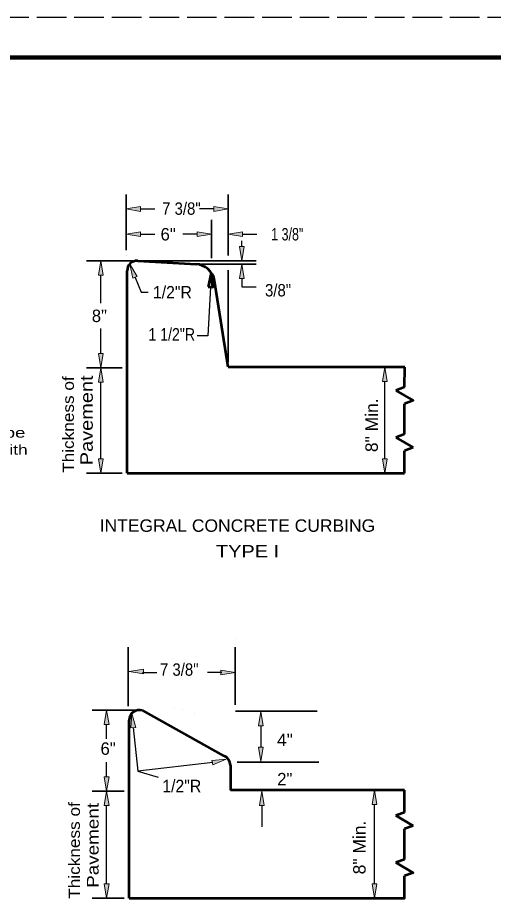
# Model space of a CAD drawing. Extents: x 36.6 to 71.9, y 0.8 to 22.8.
# Drawn here: x 48.52 to 54.49, y 11.71 to 22.78 of the extents above; entities that cross this region are included whole.
import ezdxf

# ---------------------------------------------------------------- set-up
doc = ezdxf.new("R2010")
doc.units = 0
doc.header["$LTSCALE"] = 0.062
doc.linetypes.add('LONG_DASHED', pattern=[7.5, 6, -1.5])
for name, color, linetype, lineweight in [('1', 7, 'Continuous', 13), ('3', 7, 'Continuous', 25), ('8', 7, 'Continuous', 13)]:
    doc.layers.add(name, color=color, linetype=linetype, lineweight=lineweight)

msp = doc.modelspace()

# ---------------------------------------------------------------- hatches: boundary and pattern name
at = {"layer": '1'}
for points in [[(50.06183, 20.34408), (50.06183, 20.40408), (49.88183, 20.37408), (49.88183, 20.37408)], [(50.9835, 20.34408), (50.9835, 20.40408), (51.1635, 20.37408), (51.1635, 20.37408)], [(50.06158, 20.02625), (50.06158, 20.08625), (49.88158, 20.05625), (49.88158, 20.05625)], [(50.7735, 20.02625), (50.7735, 20.08625), (50.9535, 20.05625), (50.9535, 20.05625)], [(50.7735, 20.02625), (50.7735, 20.08625), (50.9535, 20.05625), (50.9535, 20.05625)], [(51.3435, 20.02625), (51.3435, 20.08625), (51.1635, 20.05625), (51.1635, 20.05625)], [(51.36367, 19.90225), (51.30367, 19.90225), (51.33367, 19.72217), (51.33367, 19.72217)], [(49.59175, 19.54208), (49.53175, 19.54208), (49.56175, 19.72208), (49.56175, 19.72208)], [(51.36367, 19.50067), (51.30367, 19.50067), (51.33367, 19.68067), (51.33367, 19.68067)], [(49.59175, 18.55858), (49.53175, 18.55858), (49.56175, 18.37858), (49.56175, 18.37858)], [(49.59175, 18.19867), (49.53175, 18.19867), (49.56175, 18.37867), (49.56175, 18.37867)], [(53.15983, 18.20775), (53.09983, 18.20775), (53.12983, 18.38775), (53.12983, 18.38775)], [(49.59175, 17.23508), (49.53175, 17.23508), (49.56175, 17.055), (49.56175, 17.055)], [(53.15983, 17.23508), (53.09983, 17.23508), (53.12983, 17.055), (53.12983, 17.055)], [(50.09767, 14.532), (50.09767, 14.592), (49.91767, 14.562), (49.91767, 14.562)], [(51.07008, 14.52), (51.07008, 14.58), (51.25008, 14.55), (51.25008, 14.55)], [(49.66608, 13.89575), (49.60608, 13.89575), (49.63608, 14.07575), (49.63608, 14.07575)], [(51.60333, 13.87817), (51.54333, 13.87817), (51.57333, 14.05817), (51.57333, 14.05817)], [(51.60333, 13.61), (51.54333, 13.61), (51.57333, 13.43), (51.57333, 13.43)], [(49.66608, 13.23983), (49.60608, 13.23983), (49.63608, 13.05983), (49.63608, 13.05983)], [(53.03125, 12.89117), (52.97125, 12.89117), (53.00125, 13.07117), (53.00125, 13.07117)], [(49.66608, 12.87983), (49.60608, 12.87983), (49.63608, 13.05983), (49.63608, 13.05983)], [(51.61608, 12.87967), (51.55608, 12.87967), (51.58608, 13.05967), (51.58608, 13.05967)], [(49.66608, 11.89183), (49.60608, 11.89183), (49.63608, 11.71183), (49.63608, 11.71183)], [(53.03125, 11.89183), (52.97125, 11.89183), (53.00125, 11.71183), (53.00125, 11.71183)]]:
    msp.add_hatch(color=256, dxfattribs=at).paths.add_polyline_path(points)
at = {"layer": '3'}
for points in [[(49.96558, 19.50317), (50.02125, 19.5255), (49.92633, 19.68133), (49.92633, 19.68133)], [(50.91083, 19.39458), (50.97075, 19.39125), (50.95092, 19.57258), (50.95092, 19.57258)], [(49.94142, 13.85375), (50.00108, 13.85992), (49.95275, 14.03592), (49.95275, 14.03592)], [(50.95742, 13.44542), (50.97167, 13.38708), (51.13942, 13.45867), (51.13942, 13.45867)]]:
    msp.add_hatch(color=256, dxfattribs=at).paths.add_polyline_path(points)

# ---------------------------------------------------------------- linework, layer by layer
at = {"layer": '1', "linetype": 'LONG_DASHED', "lineweight": 25}
msp.add_line((71.78558, 22.77842), (36.58558, 22.77842), dxfattribs=at)
at = {"layer": '1', "lineweight": 158}
msp.add_line((71.70225, 22.27842), (39.20225, 22.27842), dxfattribs=at)
at = {"layer": '1', "lineweight": 35}
for p, q in [((49.88158, 20.11875), (49.88158, 20.55408)), ((51.1635, 19.78867), (51.1635, 20.55408)), ((49.88158, 19.857), (49.88158, 20.23625)), ((50.9535, 19.75733), (50.9535, 20.23625)), ((51.1635, 20.1125), (51.1635, 20.23625)), ((49.9635, 19.72217), (49.38175, 19.72217)), ((50.0885, 19.72225), (51.51367, 19.72225)), ((50.8215, 19.68067), (51.51367, 19.68067)), ((51.1635, 18.45025), (51.1635, 19.60558)), ((49.83142, 18.37867), (49.38175, 18.37867)), ((49.83142, 17.05508), (49.38175, 17.05508)), ((49.90567, 14.12725), (49.90567, 14.86658)), ((51.25008, 14.74908), (51.25008, 14.86658)), ((51.25008, 14.14433), (51.25008, 14.86658)), ((49.90567, 14.74908), (49.90567, 14.79217)), ((49.99758, 14.07575), (49.45608, 14.07575)), ((51.25658, 14.06308), (52.2825, 14.06308)), ((51.27567, 13.42233), (52.30158, 13.42233)), ((49.8575, 13.05983), (49.45608, 13.05983)), ((49.8575, 11.71183), (49.45608, 11.71183))]:
    msp.add_line(p, q, dxfattribs=at)
at = {"layer": '1', "lineweight": 25}
for p, q in [((50.06183, 20.37408), (50.24183, 20.37408)), ((50.9835, 20.37408), (50.8035, 20.37408)), ((50.06158, 20.05625), (50.24075, 20.05625)), ((50.7735, 20.05625), (50.5935, 20.05625)), ((51.3435, 20.05625), (51.5235, 20.05625)), ((51.33367, 19.90225), (51.33367, 19.97342)), ((49.56175, 19.18992), (49.56175, 19.54217)), ((51.33367, 19.50067), (51.33367, 19.39667)), ((51.33367, 19.39667), (51.51367, 19.39667)), ((49.56175, 18.55858), (49.56175, 18.87142)), ((49.56175, 17.23508), (49.56175, 18.19867)), ((53.12983, 17.23508), (53.12983, 18.20775)), ((50.08567, 14.55), (50.26567, 14.55)), ((51.08217, 14.54992), (50.90217, 14.54992)), ((49.63608, 13.71692), (49.63608, 13.89575)), ((51.57192, 13.87875), (51.57192, 13.60942)), ((49.63608, 13.23983), (49.63608, 13.424)), ((49.63608, 11.89183), (49.63608, 12.87983)), ((51.58458, 12.88017), (51.58458, 12.61083)), ((51.58458, 12.88017), (51.58458, 12.61083)), ((53.00125, 11.89183), (53.00125, 12.89117))]:
    msp.add_line(p, q, dxfattribs=at)
at = {"layer": '1'}
for p, q in [((50.7735, 20.05625), (50.70175, 20.05625)), ((50.9535, 19.99375), (50.9535, 19.87625)), ((49.62425, 18.37858), (49.74175, 18.37858)), ((53.06733, 18.38775), (52.94983, 18.38775)), ((53.19233, 17.05508), (53.30983, 17.05508)), ((53.06375, 13.07117), (53.18125, 13.07117)), ((49.69858, 13.05983), (49.81608, 13.05983)), ((53.06375, 11.71183), (53.18125, 11.71183))]:
    msp.add_line(p, q, dxfattribs=at)
at = {"layer": '1', "lineweight": 53}
for p, q in [((50.026, 19.72225), (50.759, 19.68067)), ((49.89392, 17.05508), (49.89392, 19.59742)), ((51.1635, 18.38775), (50.99175, 19.47)), ((53.38425, 18.38775), (51.1635, 18.38775)), ((53.37892, 18.13408), (53.38425, 18.38775)), ((53.37892, 18.13408), (53.27075, 18.09417)), ((53.37892, 17.54317), (53.37892, 17.9265)), ((53.37892, 17.54317), (53.27075, 17.50325)), ((53.27075, 17.50325), (53.48717, 17.3755)), ((53.48717, 17.3755), (53.37892, 17.33558)), ((53.37892, 17.05508), (53.37892, 17.33558)), ((49.89392, 17.05508), (53.37892, 17.05508)), ((50.08517, 14.06992), (51.10542, 13.50158)), ((49.92, 11.71183), (49.92, 13.95158)), ((51.19017, 13.38325), (51.19017, 13.07117)), ((53.37892, 13.07117), (51.19017, 13.07117)), ((53.37892, 12.79083), (53.37892, 13.07117)), ((53.37892, 12.79083), (53.27075, 12.75092)), ((53.27075, 12.75092), (53.48717, 12.62317)), ((53.48717, 12.62317), (53.37892, 12.58325)), ((53.37892, 12.19992), (53.37892, 12.58325)), ((53.37892, 12.19992), (53.27075, 12.16))]:
    msp.add_line(p, q, dxfattribs=at)
at = {"layer": '1'}
for points in [[(50.06183, 20.34408), (50.06183, 20.40408), (49.88183, 20.37408), (49.88183, 20.37408)], [(50.9835, 20.34408), (50.9835, 20.40408), (51.1635, 20.37408), (51.1635, 20.37408)], [(50.06158, 20.02625), (50.06158, 20.08625), (49.88158, 20.05625), (49.88158, 20.05625)], [(50.7735, 20.02625), (50.7735, 20.08625), (50.9535, 20.05625), (50.9535, 20.05625)], [(50.7735, 20.02625), (50.7735, 20.08625), (50.9535, 20.05625), (50.9535, 20.05625)], [(51.3435, 20.02625), (51.3435, 20.08625), (51.1635, 20.05625), (51.1635, 20.05625)], [(51.36367, 19.90225), (51.30367, 19.90225), (51.33367, 19.72217), (51.33367, 19.72217)], [(49.59175, 19.54208), (49.53175, 19.54208), (49.56175, 19.72208), (49.56175, 19.72208)], [(51.36367, 19.50067), (51.30367, 19.50067), (51.33367, 19.68067), (51.33367, 19.68067)], [(49.59175, 18.55858), (49.53175, 18.55858), (49.56175, 18.37858), (49.56175, 18.37858)], [(49.59175, 18.19867), (49.53175, 18.19867), (49.56175, 18.37867), (49.56175, 18.37867)], [(53.15983, 18.20775), (53.09983, 18.20775), (53.12983, 18.38775), (53.12983, 18.38775)], [(49.59175, 17.23508), (49.53175, 17.23508), (49.56175, 17.055), (49.56175, 17.055)], [(53.15983, 17.23508), (53.09983, 17.23508), (53.12983, 17.055), (53.12983, 17.055)], [(50.09767, 14.532), (50.09767, 14.592), (49.91767, 14.562), (49.91767, 14.562)], [(51.07008, 14.52), (51.07008, 14.58), (51.25008, 14.55), (51.25008, 14.55)], [(49.66608, 13.89575), (49.60608, 13.89575), (49.63608, 14.07575), (49.63608, 14.07575)], [(51.60333, 13.87817), (51.54333, 13.87817), (51.57333, 14.05817), (51.57333, 14.05817)], [(51.60333, 13.61), (51.54333, 13.61), (51.57333, 13.43), (51.57333, 13.43)], [(49.66608, 13.23983), (49.60608, 13.23983), (49.63608, 13.05983), (49.63608, 13.05983)], [(53.03125, 12.89117), (52.97125, 12.89117), (53.00125, 13.07117), (53.00125, 13.07117)], [(49.66608, 12.87983), (49.60608, 12.87983), (49.63608, 13.05983), (49.63608, 13.05983)], [(51.61608, 12.87967), (51.55608, 12.87967), (51.58608, 13.05967), (51.58608, 13.05967)], [(49.66608, 11.89183), (49.60608, 11.89183), (49.63608, 11.71183), (49.63608, 11.71183)], [(53.03125, 11.89183), (52.97125, 11.89183), (53.00125, 11.71183), (53.00125, 11.71183)]]:
    msp.add_lwpolyline(points, close=True, dxfattribs=at)
at = {"layer": '1', "lineweight": 53}
for points in [[(53.27075, 18.09417), (53.48717, 17.96642), (53.37892, 17.9265)], [(53.27075, 12.16), (53.48717, 12.03225), (53.37892, 11.99233)], [(49.92, 11.71183), (53.37892, 11.71183), (53.37892, 11.99233)]]:
    msp.add_lwpolyline(points, dxfattribs=at)
for centre, radius, start, end in [((50.01892, 19.59742), 0.125, 86.75472, 180), ((50.74483, 19.43108), 0.25, 8.96004, 86.75471), ((50.045, 13.95158), 0.125, 71.23187, 180), ((51.06517, 13.38325), 0.125, 0, 71.23187)]:
    msp.add_arc(centre, radius, start, end, dxfattribs=at)
at = {"layer": '3'}
msp.add_line((50.97042, 13.41858), (50.02758, 13.31117), dxfattribs=at)
at = {"layer": '3', "lineweight": 13}
for points in [[(49.96558, 19.50317), (50.02125, 19.5255), (49.92633, 19.68133), (49.92633, 19.68133)], [(49.94142, 13.85375), (50.00108, 13.85992), (49.95275, 14.03592), (49.95275, 14.03592)], [(50.95742, 13.44542), (50.97167, 13.38708), (51.13942, 13.45867), (51.13942, 13.45867)]]:
    msp.add_lwpolyline(points, close=True, dxfattribs=at)
at = {"layer": '3'}
for points in [[(49.99342, 19.51433), (50.06858, 19.32708), (50.15583, 19.32708)], [(50.94083, 19.39292), (50.90642, 18.78142), (50.77367, 18.78142)], [(49.97125, 13.85683), (50.02758, 13.31117), (50.28158, 13.23558)]]:
    msp.add_lwpolyline(points, dxfattribs=at)
at = {"layer": '3', "lineweight": 53}
msp.add_lwpolyline([(50.91083, 19.39458), (50.97075, 19.39125), (50.95092, 19.57258), (50.95092, 19.57258)], close=True, dxfattribs=at)
at = {"layer": '8'}
for p, q in [((51.1635, 20.37408), (51.16358, 20.37408)), ((49.88158, 20.05625), (49.88167, 20.05625)), ((50.9535, 20.05625), (50.95358, 20.05625)), ((50.9535, 20.05625), (50.95358, 20.05625)), ((51.1635, 20.05625), (51.16358, 20.05625)), ((51.1635, 20.05), (51.16358, 20.05)), ((49.56175, 19.72217), (49.56183, 19.72217)), ((49.88158, 19.7945), (49.88167, 19.7945)), ((50.026, 19.72225), (50.02608, 19.72225)), ((50.026, 19.72217), (50.02608, 19.72217)), ((50.759, 19.68067), (50.75908, 19.68067)), ((50.9535, 19.69483), (50.95358, 19.69483)), ((51.33367, 19.68067), (51.33375, 19.68067)), ((49.56175, 18.37867), (49.56183, 18.37867)), ((49.56175, 18.37858), (49.56183, 18.37858)), ((49.89392, 18.37867), (49.894, 18.37867)), ((51.1635, 18.38775), (51.16358, 18.38775)), ((53.12983, 18.38775), (53.12992, 18.38775)), ((53.12983, 18.38775), (53.12992, 18.38775)), ((49.89392, 17.05508), (49.894, 17.05508)), ((53.12983, 17.05508), (53.12992, 17.05508)), ((51.25008, 14.972), (51.25017, 14.972)), ((49.90567, 14.46358), (49.90575, 14.46358)), ((49.90567, 14.46358), (49.90575, 14.46358)), ((51.25008, 14.46358), (51.25017, 14.46358)), ((51.25008, 14.46358), (51.25017, 14.46358)), ((49.63608, 14.07575), (49.63617, 14.07575)), ((49.90567, 14.12883), (49.90575, 14.12883)), ((50.49133, 14.09167), (50.49142, 14.09167)), ((50.59075, 14.087), (50.59083, 14.087)), ((50.74583, 14.03533), (50.74592, 14.03533)), ((51.57333, 14.03533), (51.57342, 14.03533)), ((51.25008, 13.07117), (51.25017, 13.07117)), ((53.00125, 13.07117), (53.00133, 13.07117)), ((53.00125, 13.07117), (53.00133, 13.07117)), ((49.63608, 13.05983), (49.63617, 13.05983)), ((49.63608, 13.05983), (49.63617, 13.05983)), ((49.92, 13.05983), (49.92008, 13.05983)), ((49.92, 11.71183), (49.92008, 11.71183)), ((53.00125, 11.71183), (53.00133, 11.71183))]:
    msp.add_line(p, q, dxfattribs=at)

# ---------------------------------------------------------------- texts
at = {"layer": '1'}
for s, width, p in [('7 3/8"', 0.9, (50.33242, 20.30058)), ('1 3/8"', 0.75, (51.7035, 19.97817)), ('7 3/8"', 0.9, (50.3055, 14.50775)), ('4"', 1.05, (51.77617, 13.624))]:
    msp.add_text(s, height=0.1562, dxfattribs=dict(at, width=width)).set_placement(p)
for s, p in [('6"', (50.31342, 19.97817)), ('8"', (49.44975, 18.95267)), ('6"', (49.55917, 13.51475)), ('2"', (51.77867, 13.13108))]:
    msp.add_text(s, height=0.1562, dxfattribs=at).set_placement(p)
for s, height, width, p in [('Thickness of', 0.1406, 1.15, (49.22392, 17.05783)), ('8" Min.', 0.1562, 1.05, (53.04317, 17.3185)), ('Thickness of', 0.1406, 1.15, (49.29967, 11.70583)), ('8" Min.', 0.1562, 1.05, (52.889, 12.01292))]:
    msp.add_text(s, height=height, rotation=90, dxfattribs=dict(at, width=width)).set_placement(p)
at = {"layer": '3'}
for s, height, width, p in [('1/2"R', 0.1562, 0.95, (50.21742, 19.24892)), ('3/8"', 0.1562, 0.9, (51.62558, 19.2745)), ('1 1/2"R', 0.1562, 0.85, (50.16058, 18.72025)), ('Edge to be', 0.125, 1.4, (47.48367, 17.50025)), ('painted with', 0.125, 1.3, (47.48367, 17.286)), ('INTEGRAL CONCRETE CURBING', 0.1562, 1.05, (49.549, 16.31708)), ('TYPE I', 0.1562, 1.2, (51.00925, 15.99442)), ('1/2"R', 0.1562, 0.95, (50.33517, 13.045))]:
    msp.add_text(s, height=height, dxfattribs=dict(at, width=width)).set_placement(p)
at = {"layer": '3', "width": 1.2}
for height, p in [(0.1562, (49.46167, 17.15375)), (0.1474, (49.535, 11.84417))]:
    msp.add_text('Pavement', height=height, rotation=90, dxfattribs=at).set_placement(p)

doc.saveas('drawing.dxf')
